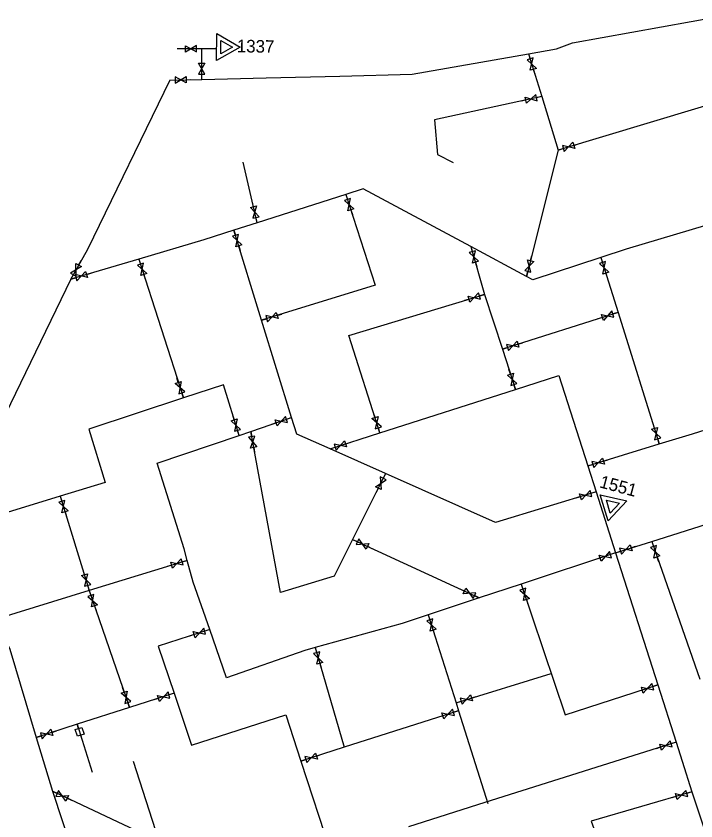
# Model space of a CAD drawing. Extents: x 349903 to 372392, y 368574 to 383062.
# Drawn here: x 362258.2 to 362528, y 372320.7 to 372640.2 of the extents above; entities that cross this region are included whole.
import ezdxf

# ---------------------------------------------------------------- set-up
doc = ezdxf.new("R2010")
doc.units = 0
for name, color, linetype in [('Niveau 1', 7, 'Continuous'), ('Niveau 10', 7, 'Continuous'), ('Niveau 2', 7, 'Continuous'), ('Niveau 3', 7, 'Continuous')]:
    doc.layers.add(name, color=color, linetype=linetype)

msp = doc.modelspace()

# ---------------------------------------------------------------- linework, layer by layer
at = {"layer": 'Niveau 1'}
for p, q in [((362325.389, 372627.134), (362323.488, 372627.118)), ((362331.873, 372627.191), (362329.769, 372627.173)), ((362461.547, 372625.195), (362462.176, 372623.187)), ((362331.858, 372621.519), (362331.853, 372623.42)), ((362463.486, 372619.008), (362464.055, 372617.194)), ((362331.873, 372615.035), (362331.868, 372617.139)), ((362319.186, 372614.753), (362321.29, 372614.801)), ((362325.668, 372614.901), (362327.569, 372614.945)), ((362460.475, 372606.803), (362458.618, 372606.393)), ((362466.806, 372608.202), (362464.751, 372607.748)), ((362473.374, 372586.974), (362475.389, 372587.58)), ((362479.583, 372588.842), (362481.404, 372589.39)), ((362389.105, 372569.361), (362389.745, 372567.356)), ((362352.391, 372564.494), (362351.955, 372566.345)), ((362391.079, 372563.185), (362391.658, 372561.374)), ((362353.875, 372558.182), (362353.393, 372560.231)), ((362344.629, 372555.166), (362345.249, 372553.155)), ((362346.542, 372548.971), (362347.103, 372547.154)), ((362438.679, 372548.67), (362439.265, 372546.649)), ((362462.432, 372543.101), (362462.915, 372544.94)), ((362283.054, 372541.347), (362283.977, 372543.009)), ((362306.933, 372543.706), (362307.569, 372541.7)), ((362440.484, 372542.442), (362441.014, 372540.616)), ((362490.279, 372544.301), (362490.923, 372542.298)), ((362460.785, 372536.83), (362461.32, 372538.865)), ((362279.905, 372535.679), (362280.928, 372537.518)), ((362279.905, 372535.679), (362281.919, 372536.289)), ((362286.11, 372537.561), (362287.929, 372538.113)), ((362308.894, 372537.526), (362309.47, 372535.714)), ((362492.264, 372538.128), (362492.846, 372536.318)), ((362444.159, 372529.671), (362442.147, 372529.056)), ((362437.959, 372527.774), (362436.141, 372527.218)), ((362497.102, 372522.544), (362495.099, 372521.899)), ((362355.648, 372519.395), (362357.659, 372520.014)), ((362361.844, 372521.305), (362363.661, 372521.865)), ((362490.931, 372520.555), (362489.121, 372519.972)), ((362457.411, 372509.892), (362459.223, 372510.468)), ((362451.232, 372507.928), (362453.238, 372508.565)), ((362454.395, 372498.068), (362453.794, 372499.872)), ((362322.571, 372494.719), (362321.978, 372496.526)), ((362456.441, 372491.915), (362455.777, 372493.912)), ((362324.591, 372488.558), (362323.936, 372490.558)), ((362344.779, 372479.878), (362344.206, 372481.691)), ((362400.651, 372480.86), (362400.072, 372482.671)), ((362361.419, 372478.651), (362359.62, 372478.034)), ((362367.552, 372480.755), (362365.561, 372480.073)), ((362511.571, 372476.511), (362511.011, 372478.328)), ((362346.734, 372473.696), (362346.1, 372475.703)), ((362351.341, 372475.258), (362351.723, 372473.189)), ((362402.623, 372474.683), (362401.983, 372476.688)), ((362513.482, 372470.315), (362512.862, 372472.326)), ((362352.519, 372468.882), (362352.864, 372467.012)), ((362382.8, 372468.336), (362384.804, 372468.978)), ((362388.975, 372470.314), (362390.786, 372470.894)), ((362485.106, 372461.557), (362487.118, 372462.173)), ((362491.306, 372463.455), (362493.124, 372464.012)), ((362404.82, 372458.525), (362403.882, 372456.641)), ((362401.931, 372452.72), (362401.084, 372451.018)), ((362275.668, 372449.533), (362276.293, 372447.523)), ((362482.199, 372449.365), (362480.387, 372448.79)), ((362488.379, 372451.327), (362486.373, 372450.691)), ((362277.593, 372443.341), (362278.158, 372441.526)), ((362391.734, 372432.406), (362393.641, 372431.517)), ((362510.466, 372431.553), (362511.147, 372429.562)), ((362397.611, 372429.667), (362399.334, 372428.864)), ((362496.155, 372427.026), (362494.156, 372426.368)), ((362496.155, 372427.026), (362498.149, 372427.7)), ((362502.298, 372429.101), (362504.099, 372429.711)), ((362324.126, 372423.475), (362326.146, 372424.094)), ((362489.996, 372424.999), (362488.19, 372424.404)), ((362512.565, 372425.418), (362513.181, 372423.62)), ((362319.946, 372422.195), (362318.129, 372421.639)), ((362285.361, 372418.385), (362284.825, 372420.209)), ((362287.19, 372412.164), (362286.597, 372414.183)), ((362458.606, 372414.672), (362459.292, 372412.682)), ((362287.188, 372412.164), (362287.874, 372410.174)), ((362436.121, 372411.917), (362434.393, 372412.711)), ((362442.014, 372409.212), (362440.102, 372410.09)), ((362460.72, 372408.542), (362461.339, 372406.745)), ((362289.302, 372406.034), (362289.922, 372404.237)), ((362421.769, 372402.511), (362422.408, 372400.506)), ((362335.031, 372396.6), (362333.03, 372395.95)), ((362423.74, 372396.334), (362424.319, 372394.523)), ((362328.865, 372394.596), (362327.057, 372394.008)), ((362376.868, 372389.445), (362377.476, 372387.43)), ((362378.743, 372383.238), (362379.292, 372381.418)), ((362301.061, 372371.78), (362300.443, 372373.578)), ((362506.757, 372372.619), (362504.947, 372372.034)), ((362512.927, 372374.611), (362510.924, 372373.965)), ((362314.706, 372369.313), (362312.896, 372368.728)), ((362320.876, 372371.305), (362318.873, 372370.659)), ((362438.989, 372369.484), (362440.803, 372370.052)), ((362303.171, 372365.649), (362302.487, 372367.639)), ((362432.801, 372367.547), (362434.809, 372368.175)), ((362433.791, 372364.408), (362431.788, 372363.763)), ((362427.62, 372362.419), (362425.81, 372361.836)), ((362272.366, 372355.807), (362274.176, 372356.389)), ((362266.193, 372353.822), (362268.196, 372354.466)), ((362520.21, 372351.85), (362518.204, 372351.214)), ((362377.384, 372346.395), (362379.194, 372346.975)), ((362514.029, 372349.89), (362512.217, 372349.315)), ((362371.209, 372344.417), (362373.213, 372345.059)), ((362272.581, 372332.449), (362274.48, 372331.543)), ((362526.463, 372332.136), (362524.441, 372331.553)), ((362278.433, 372329.658), (362280.15, 372328.839)), ((362520.233, 372330.338), (362518.406, 372329.811))]:
    msp.add_line(p, q, dxfattribs=at)
for points in [[(362325.404, 372625.866), (362325.375, 372628.389), (362329.766, 372625.904), (362329.752, 372628.428)], [(362330.59, 372621.512), (362333.113, 372621.526), (362330.6, 372617.15), (362333.123, 372617.148)], [(362464.695, 372619.391), (362462.29, 372618.629), (362463.391, 372623.553), (362460.98, 372622.806)], [(362325.635, 372616.169), (362325.701, 372613.647), (362321.275, 372616.069), (362321.324, 372613.546)], [(362460.752, 372605.566), (362460.2, 372608.028), (362465.011, 372606.507), (362464.475, 372608.973)], [(362479.214, 372590.055), (362479.948, 372587.642), (362475.037, 372588.799), (362475.756, 372586.38)], [(362392.286, 372563.575), (362389.885, 372562.799), (362390.958, 372567.729), (362388.552, 372566.969)], [(362351.157, 372564.2), (362353.611, 372564.785), (362352.155, 372559.954), (362354.614, 372560.524)], [(362347.752, 372549.349), (362345.344, 372548.597), (362346.466, 372553.516), (362344.052, 372552.779)], [(362441.701, 372542.799), (362439.28, 372542.089), (362440.487, 372546.989), (362438.061, 372546.294)], [(362281.943, 372541.959), (362284.153, 372540.741), (362279.825, 372538.146), (362282.027, 372536.914)], [(362310.102, 372537.913), (362307.699, 372537.142), (362308.782, 372542.071), (362306.375, 372541.315)], [(362461.205, 372543.419), (362463.647, 372542.786), (362460.097, 372539.201), (362462.535, 372538.552)], [(362493.47, 372538.52), (362491.07, 372537.74), (362492.135, 372542.673), (362489.73, 372541.908)], [(362285.738, 372538.773), (362286.478, 372536.361), (362281.564, 372537.507), (362282.289, 372535.09)], [(362438.334, 372526.563), (362437.588, 372528.973), (362442.504, 372527.839), (362441.774, 372530.254)], [(362361.467, 372522.515), (362362.218, 372520.106), (362357.299, 372521.231), (362358.034, 372518.817)], [(362491.324, 372519.349), (362490.542, 372521.748), (362495.475, 372520.687), (362494.708, 372523.092)], [(362457.024, 372511.099), (362457.795, 372508.697), (362452.867, 372509.778), (362453.623, 372507.371)], [(362453.193, 372497.663), (362455.584, 372498.467), (362454.569, 372493.525), (362456.966, 372494.314)], [(362321.367, 372494.32), (362323.762, 372495.114), (362322.726, 372490.176), (362325.126, 372490.954)], [(362361.834, 372477.453), (362361.008, 372479.837), (362365.96, 372478.868), (362365.149, 372481.258)], [(362399.444, 372480.47), (362401.845, 372481.245), (362400.771, 372476.315), (362403.177, 372477.075)], [(362343.571, 372479.492), (362345.975, 372480.26), (362344.886, 372475.333), (362347.295, 372476.086)], [(362510.361, 372476.133), (362512.77, 372476.885), (362511.646, 372471.966), (362514.06, 372472.701)], [(362353.765, 372469.116), (362351.285, 372468.65), (362352.973, 372473.405), (362350.49, 372472.955)], [(362388.584, 372471.52), (362389.362, 372469.12), (362384.431, 372470.19), (362385.193, 372467.784)], [(362490.931, 372464.666), (362491.677, 372462.256), (362486.76, 372463.39), (362487.491, 372460.974)], [(362403.068, 372452.159), (362400.806, 372453.276), (362405.011, 372456.064), (362402.756, 372457.195)], [(362482.587, 372448.158), (362481.815, 372450.56), (362486.744, 372449.477), (362485.988, 372451.885)], [(362278.803, 372443.722), (362276.396, 372442.965), (362277.508, 372447.887), (362275.096, 372447.145)], [(362398.143, 372430.818), (362397.084, 372428.528), (362394.19, 372432.661), (362393.116, 372430.377)], [(362501.887, 372430.302), (362502.703, 372427.913), (362497.755, 372428.906), (362498.556, 372426.512)], [(362513.763, 372425.832), (362511.379, 372425.009), (362512.351, 372429.96), (362509.961, 372429.15)], [(362490.397, 372423.795), (362489.6, 372426.19), (362494.54, 372425.159), (362493.758, 372427.559)], [(362320.321, 372420.984), (362319.575, 372423.394), (362324.492, 372422.261), (362323.761, 372424.676)], [(362284.146, 372418.023), (362286.564, 372418.743), (362285.376, 372413.839), (362287.799, 372414.543)], [(362435.596, 372410.763), (362436.642, 372413.06), (362439.56, 372408.943), (362440.62, 372411.233)], [(362461.917, 372408.959), (362459.534, 372408.129), (362460.495, 372413.083), (362458.107, 372412.268)], [(362290.499, 372406.452), (362288.117, 372405.621), (362289.077, 372410.574), (362286.689, 372409.759)], [(362424.947, 372396.723), (362422.546, 372395.949), (362423.621, 372400.879), (362421.215, 372400.119)], [(362329.261, 372393.391), (362328.473, 372395.788), (362333.409, 372394.739), (362332.636, 372397.142)], [(362379.955, 372383.608), (362377.542, 372382.871), (362378.694, 372387.784), (362376.276, 372387.062)], [(362507.15, 372371.413), (362506.367, 372373.812), (362511.301, 372372.753), (362510.533, 372375.157)], [(362299.864, 372371.364), (362302.247, 372372.192), (362301.283, 372367.239), (362303.672, 372368.053)], [(362315.099, 372368.107), (362314.316, 372370.506), (362319.25, 372369.447), (362318.482, 372371.851)], [(362438.606, 372370.693), (362439.368, 372368.288), (362434.444, 372369.39), (362435.19, 372366.979)], [(362428.013, 372361.213), (362427.231, 372363.612), (362432.164, 372362.551), (362431.397, 372364.956)], [(362271.974, 372357.013), (362272.754, 372354.613), (362267.821, 372355.678), (362268.586, 372353.273)], [(362514.417, 372348.682), (362513.646, 372351.085), (362518.574, 372350.001), (362517.819, 372352.409)], [(362376.993, 372347.602), (362377.77, 372345.201), (362372.839, 372346.271), (362373.602, 372343.865)], [(362278.976, 372330.804), (362277.897, 372328.523), (362275.039, 372332.682), (362273.945, 372330.407)], [(362520.589, 372329.121), (362519.881, 372331.543), (362524.779, 372330.33), (362524.087, 372332.757)]]:
    msp.add_lwpolyline(points, close=True, dxfattribs=at)
at = {"layer": 'Niveau 10'}
for p, q in [((362331.873, 372627.191), (362322.112, 372627.191)), ((362337.88, 372627.191), (362331.873, 372627.191)), ((362331.873, 372615.035), (362331.873, 372627.191)), ((362353.908, 372558.128), (362348.252, 372582.193)), ((362306.933, 372543.706), (362324.591, 372488.558)), ((362490.279, 372544.301), (362497.102, 372522.544)), ((362497.102, 372522.544), (362451.232, 372507.928)), ((362497.102, 372522.544), (362513.482, 372470.315)), ((362275.668, 372449.533), (362287.19, 372412.164)), ((362391.734, 372432.406), (362442.014, 372409.212)), ((362326.146, 372424.094), (362287.19, 372412.164)), ((362287.189, 372412.164), (362249.62, 372400.582)), ((362287.189, 372412.164), (362303.171, 372365.649)), ((362421.769, 372402.511), (362432.801, 372367.547)), ((362376.868, 372389.445), (362388.427, 372349.915)), ((362432.801, 372367.547), (362470.519, 372379.221)), ((362320.876, 372371.305), (362303.171, 372365.649)), ((362432.801, 372367.547), (362433.791, 372364.408)), ((362303.171, 372365.649), (362282.438, 372359.018)), ((362433.791, 372364.408), (362388.427, 372349.915)), ((362433.791, 372364.408), (362445.398, 372327.622)), ((362282.438, 372359.018), (362266.193, 372353.822)), ((362282.438, 372359.018), (362288.409, 372340.069)), ((362388.427, 372349.915), (362371.209, 372344.417)), ((362304.645, 372344.422), (362314.913, 372312.455))]:
    msp.add_line(p, q, dxfattribs=at)
for points in [[(362461.547, 372625.195), (362472.724, 372627.143), (362478.99, 372629.524), (362537.944, 372640.152)], [(362537.944, 372640.152), (362546.419, 372608.954), (362473.374, 372586.974)], [(362331.873, 372615.035), (362357.385, 372615.6), (362386.721, 372616.361), (362415.344, 372617.144), (362461.547, 372625.195)], [(362461.547, 372625.195), (362466.806, 372608.202)], [(362319.186, 372614.753), (362286.498, 372547.501), (362279.905, 372535.679)], [(362319.186, 372614.753), (362331.873, 372615.035)], [(362466.806, 372608.202), (362424.206, 372598.928), (362425.445, 372585.266), (362431.64, 372582.073)], [(362466.806, 372608.202), (362473.374, 372586.974)], [(362473.374, 372586.974), (362473.408, 372586.863), (362460.785, 372536.83)], [(362438.679, 372548.67), (362395.962, 372571.549), (362389.105, 372569.361)], [(362389.105, 372569.361), (362353.908, 372558.128)], [(362389.105, 372569.361), (362400.661, 372533.381), (362355.648, 372519.395)], [(362353.908, 372558.128), (362344.629, 372555.166)], [(362539.045, 372559.186), (362500.382, 372547.592), (362490.279, 372544.301)], [(362344.629, 372555.166), (362332.669, 372551.35), (362306.933, 372543.706)], [(362355.648, 372519.395), (362344.629, 372555.166)], [(362460.785, 372536.83), (362438.679, 372548.67)], [(362438.679, 372548.67), (362444.159, 372529.671)], [(362306.933, 372543.706), (362279.905, 372535.679)], [(362490.279, 372544.301), (362463.267, 372535.501), (362460.785, 372536.83)], [(362279.905, 372535.679), (362245.71, 372465.405), (362235.182, 372444.101)], [(362402.623, 372474.683), (362390.294, 372513.381), (362444.159, 372529.671)], [(362444.159, 372529.671), (362451.232, 372507.928)], [(362367.552, 372480.755), (362355.648, 372519.395)], [(362451.232, 372507.928), (362456.441, 372491.915)], [(362456.441, 372491.915), (362473.63, 372497.419), (362485.106, 372461.557)], [(362346.734, 372473.696), (362340.452, 372493.782), (362324.591, 372488.558)], [(362402.623, 372474.683), (362456.441, 372491.915)], [(362324.591, 372488.558), (362287.022, 372476.182), (362293.48, 372454.982), (362275.668, 372449.533)], [(362351.341, 372475.258), (362367.552, 372480.755)], [(362382.8, 372468.336), (362369.56, 372474.235), (362367.552, 372480.755)], [(362513.482, 372470.315), (362526.617, 372474.369), (362545.835, 372480.357)], [(362346.734, 372473.696), (362351.341, 372475.258)], [(362391.734, 372432.406), (362384.445, 372417.858), (362363.086, 372411.269), (362351.341, 372475.258)], [(362382.8, 372468.336), (362402.623, 372474.683)], [(362326.146, 372424.094), (362324.902, 372428.667), (362314.136, 372462.643), (362346.734, 372473.696)], [(362404.82, 372458.525), (362382.8, 372468.336)], [(362485.106, 372461.557), (362513.482, 372470.315)], [(362485.106, 372461.557), (362488.379, 372451.327)], [(362404.82, 372458.525), (362391.734, 372432.406)], [(362488.379, 372451.327), (362448.509, 372439.06), (362404.82, 372458.525)], [(362275.668, 372449.533), (362237.321, 372437.801)], [(362488.379, 372451.327), (362496.155, 372427.026)], [(362237.321, 372437.801), (362249.852, 372400.889), (362255.743, 372388.781), (362266.193, 372353.822)], [(362510.466, 372431.553), (362535.133, 372439.355)], [(362496.155, 372427.026), (362510.466, 372431.553)], [(362510.466, 372431.553), (362529.586, 372376.926)], [(362496.155, 372427.026), (362458.606, 372414.672)], [(362496.155, 372427.026), (362512.927, 372374.611)], [(362335.031, 372396.6), (362328.49, 372415.476), (362326.146, 372424.094)], [(362458.606, 372414.672), (362442.014, 372409.212)], [(362458.606, 372414.672), (362476.101, 372362.822), (362512.927, 372374.611)], [(362442.014, 372409.212), (362421.769, 372402.511)], [(362421.769, 372402.511), (362411.427, 372399.088), (362376.868, 372389.445)], [(362335.031, 372396.6), (362314.613, 372390.021), (362320.876, 372371.305)], [(362376.868, 372389.445), (362372.75, 372388.295), (362341.649, 372377.503), (362335.031, 372396.6)], [(362512.927, 372374.611), (362520.21, 372351.85)], [(362320.876, 372371.305), (362327.772, 372350.702), (362365.253, 372362.702), (362371.209, 372344.417)], [(362266.193, 372353.822), (362272.581, 372332.449)], [(362520.21, 372351.85), (362444.202, 372328.022), (362413.947, 372318.356)], [(362520.21, 372351.85), (362522.606, 372344.365)], [(362371.209, 372344.417), (362382.928, 372308.446)], [(362522.606, 372344.365), (362526.463, 372332.136)], [(362314.913, 372312.455), (362272.581, 372332.449)], [(362272.581, 372332.449), (362280.706, 372308.017)], [(362526.463, 372332.136), (362486.468, 372320.502), (362490.677, 372308.847)], [(362526.463, 372332.136), (362543.088, 372282.102), (362544.393, 372278.437)]]:
    msp.add_lwpolyline(points, dxfattribs=at)
at = {"layer": 'Niveau 2'}
for points in [[(362347.086, 372627.83), (362337.744, 372622.494), (362337.795, 372633.252)], [(362344.104, 372627.81), (362339.434, 372625.144), (362339.461, 372630.523)], [(362500.558, 372447.689), (362493.211, 372439.83), (362490.079, 372450.122)], [(362497.715, 372446.788), (362494.042, 372442.86), (362492.478, 372448.007)]]:
    msp.add_lwpolyline(points, close=True, dxfattribs=at)
at = {"layer": 'Niveau 3'}
for p, q in [((362282.962, 372357.357), (362282.438, 372359.018)), ((362283.789, 372354.73), (362284.285, 372353.158))]:
    msp.add_line(p, q, dxfattribs=at)
msp.add_lwpolyline([(362282.512, 372354.327), (362281.684, 372356.954), (362284.304, 372357.78), (362285.132, 372355.153)], close=True, dxfattribs=at)

# ---------------------------------------------------------------- texts
at = {"layer": 'Niveau 2'}
for s, rotation, p in [('1337', 359, (362345.771, 372625.812)), ('1551', 344.95934, (362489.437, 372453.123))]:
    msp.add_text(s, height=5, rotation=rotation, dxfattribs=at).set_placement(p)

doc.saveas('drawing.dxf')
